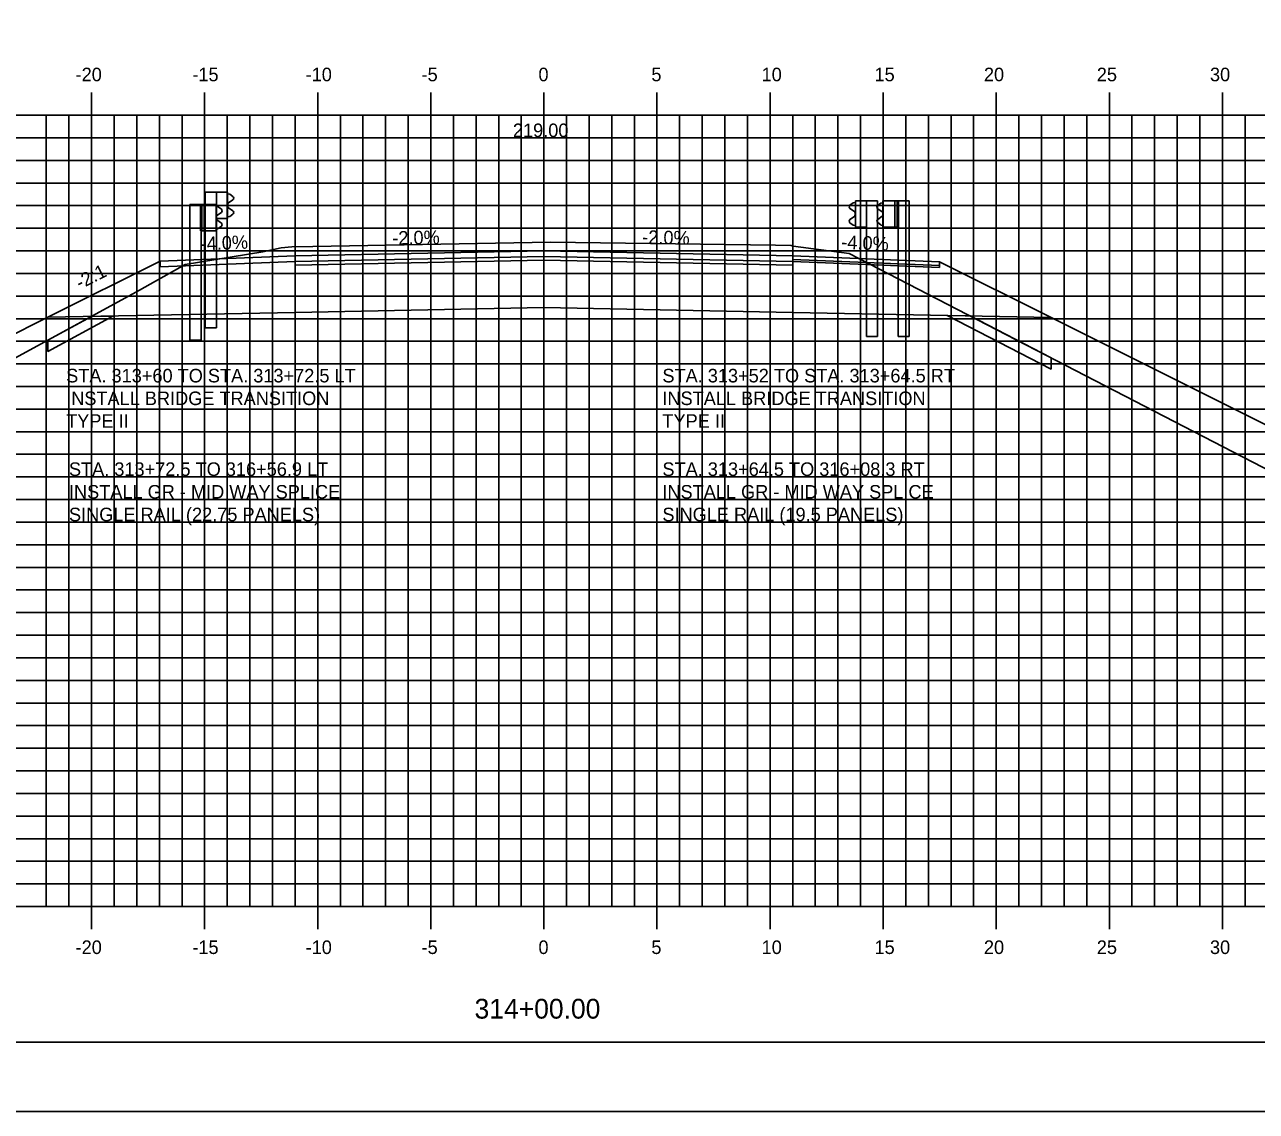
# Model space of a CAD drawing. Extents: x 1138320 to 1138490, y 608981 to 609091.
# Drawn here: x 1138379.7 to 1138434.2, y 608981.3 to 609029.3 of the extents above; entities that cross this region are included whole.
import ezdxf

# ---------------------------------------------------------------- set-up
doc = ezdxf.new("R2010")
doc.units = 0
for name, color, linetype in [('ANNOTATION', 7, 'Continuous'), ('BORDER', 7, 'Continuous'), ('D_Guardrail_Beam_Lt', 7, 'Continuous'), ('D_Guardrail_Beam_Rt', 7, 'Continuous'), ('D_Guardrail_ConcBarrier', 7, 'Continuous'), ('D_Roadway_Centerline', 7, 'Continuous'), ('D_Roadway_Centerline_Text', 7, 'Continuous'), ('D_Roadway_Edge_Shoulder', 7, 'Continuous'), ('D_Roadway_Edge_TW', 7, 'Continuous'), ('D_Roadway_Pavement', 7, 'Continuous'), ('D_Roadway_SlopeLines', 7, 'Continuous'), ('D_Roadway_SubGrade', 7, 'Continuous'), ('H_V ANNOTATION', 7, 'Continuous'), ('MAJOR', 7, 'Continuous'), ('MINOR', 7, 'Continuous'), ('PLOT BOUNDARY', 7, 'Continuous'), ('S_Guardrail_Beam', 7, 'Continuous'), ('S_Roadway_Centerline', 7, 'Continuous'), ('SHADING', 7, 'Continuous')]:
    doc.layers.add(name, color=color, linetype=linetype)

msp = doc.modelspace()

# ---------------------------------------------------------------- linework, layer by layer
msp.add_lwpolyline([(1138342.969, 608997.503), (1138378.753, 609015.395), (1138380.753, 609016.395), (1138385.713, 609018.875), (1138385.714, 609018.875), (1138391.679, 609019.113), (1138402.679, 609019.333), (1138413.679, 609019.113), (1138420.167, 609018.854), (1138425.105, 609016.385), (1138427.105, 609015.385), (1138461.719, 608998.078)])
at = {"layer": 'BORDER'}
msp.add_lwpolyline([(1138327.679, 608984.335), (1138487.679, 608984.335), (1138487.679, 609089.335), (1138327.679, 609089.335)], close=True, dxfattribs=at)
at = {"layer": 'D_Guardrail_Beam_Lt'}
for p, q in [((1138387.026, 609021.382), (1138387.026, 609015.382)), ((1138387.497, 609021.382), (1138387.026, 609021.382)), ((1138388.184, 609021.382), (1138387.497, 609021.382)), ((1138387.497, 609021.382), (1138387.497, 609020.216)), ((1138387.559, 609021.382), (1138387.559, 609020.216)), ((1138387.664, 609021.382), (1138387.664, 609020.216)), ((1138388.184, 609020.216), (1138388.184, 609021.382)), ((1138388.184, 609021.299), (1138388.259, 609021.285)), ((1138388.274, 609021.278), (1138388.418, 609021.178)), ((1138388.189, 609020.834), (1138388.189, 609020.764)), ((1138388.418, 609021.035), (1138388.223, 609020.899)), ((1138388.223, 609020.7), (1138388.418, 609020.563)), ((1138387.497, 609020.216), (1138388.184, 609020.216)), ((1138387.518, 609015.382), (1138387.518, 609020.216)), ((1138388.259, 609020.314), (1138388.184, 609020.299)), ((1138388.418, 609020.42), (1138388.274, 609020.32)), ((1138387.518, 609015.382), (1138387.026, 609015.382))]:
    msp.add_line(p, q, dxfattribs=at)
for centre, major_axis, start_param, end_param in [((1138388.251, 609021.244), (0.0417, 0), 0.959931, 1.376053), ((1138388.368, 609021.106), (0.0877, 0), 5.323254, 7.243116), ((1138388.268, 609020.834), (-0.0789, 0), 5.323254, 6.283185), ((1138388.268, 609020.764), (-0.0789, 0), 6.283185, 7.243116), ((1138388.251, 609020.354), (0.0417, 0), 4.907132, 5.323254), ((1138388.368, 609020.492), (0.0877, 0), 5.323254, 7.243116)]:
    msp.add_ellipse(centre, major_axis=major_axis, ratio=0.995501, start_param=start_param, end_param=end_param, dxfattribs=at)
at = {"layer": 'D_Guardrail_Beam_Rt'}
for p, q in [((1138417.58, 609021.44), (1138417.437, 609021.34)), ((1138417.437, 609021.197), (1138417.632, 609021.061)), ((1138417.67, 609021.462), (1138417.596, 609021.447)), ((1138417.632, 609020.862), (1138417.437, 609020.726)), ((1138417.666, 609020.997), (1138417.666, 609020.926)), ((1138417.437, 609020.583), (1138417.58, 609020.483)), ((1138417.596, 609020.476), (1138417.67, 609020.462))]:
    msp.add_line(p, q, dxfattribs=at)
for centre, major_axis, start_param, end_param in [((1138417.487, 609021.269), (-0.0877, 0), 5.323254, 7.243116), ((1138417.604, 609021.406), (-0.0417, 0), 4.907132, 5.323254), ((1138417.487, 609020.654), (-0.0877, 0), 5.323254, 7.243116), ((1138417.587, 609020.997), (0.0789, 0), 0, 0.959931), ((1138417.587, 609020.926), (0.0789, 0), 5.323254, 6.283185), ((1138417.604, 609020.517), (-0.0417, 0), 0.959931, 1.376053)]:
    msp.add_ellipse(centre, major_axis=major_axis, ratio=0.995501, start_param=start_param, end_param=end_param, dxfattribs=at)
at = {"layer": 'D_Guardrail_ConcBarrier'}
for p, q in [((1138417.67, 609021.545), (1138418.358, 609021.545)), ((1138417.67, 609020.378), (1138417.67, 609021.545)), ((1138418.191, 609021.545), (1138418.191, 609020.378)), ((1138418.295, 609021.545), (1138418.295, 609020.378)), ((1138418.358, 609021.545), (1138418.828, 609021.545)), ((1138418.358, 609021.545), (1138418.358, 609020.378)), ((1138418.828, 609021.545), (1138418.828, 609015.545)), ((1138418.358, 609020.378), (1138417.67, 609020.378)), ((1138418.337, 609015.545), (1138418.337, 609020.378)), ((1138418.337, 609015.545), (1138418.828, 609015.545))]:
    msp.add_line(p, q, dxfattribs=at)
at = {"layer": 'D_Roadway_Edge_Shoulder'}
for points in [[(1138391.679, 609019.113), (1138385.714, 609018.875), (1138385.714, 609018.625), (1138391.679, 609018.863)], [(1138413.679, 609019.113), (1138420.167, 609018.854), (1138420.167, 609018.687), (1138413.679, 609018.947)], [(1138413.679, 609019.113), (1138420.167, 609018.854), (1138420.167, 609018.604), (1138413.679, 609018.863)]]:
    msp.add_lwpolyline(points, close=True, dxfattribs=at)
at = {"layer": 'D_Roadway_Edge_TW'}
msp.add_lwpolyline([(1138391.679, 609018.863), (1138391.679, 609019.113), (1138402.679, 609019.333), (1138413.679, 609019.113), (1138413.679, 609018.863), (1138402.679, 609019.083)], close=True, dxfattribs=at)
at = {"layer": 'D_Roadway_Pavement'}
msp.add_lwpolyline([(1138391.679, 609018.697), (1138391.679, 609018.863), (1138402.679, 609019.083), (1138413.679, 609018.863), (1138413.679, 609018.697), (1138402.679, 609018.917)], close=True, dxfattribs=at)
at = {"layer": 'D_Roadway_SlopeLines'}
for points in [[(1138383.94, 609017.125), (1138383.94, 609017.125)], [(1138423.716, 609017.079), (1138461.719, 608998.078)], [(1138380.753, 609016.395), (1138378.753, 609015.395)], [(1138380.753, 609015.386), (1138380.753, 609014.886), (1138383.623, 609016.452)], [(1138425.105, 609014.602), (1138425.105, 609014.102), (1138420.512, 609016.477)], [(1138425.105, 609016.385), (1138427.105, 609015.385)], [(1138427.105, 609015.385), (1138461.719, 608998.078)]]:
    msp.add_lwpolyline(points, dxfattribs=at)
at = {"layer": 'D_Roadway_SubGrade'}
for points in [[(1138391.679, 609018.697), (1138391.679, 609018.863), (1138385.714, 609018.625), (1138385.714, 609018.875), (1138385.713, 609018.875), (1138380.753, 609016.395), (1138391.679, 609016.613)], [(1138391.679, 609016.613), (1138391.679, 609018.697), (1138402.679, 609018.917), (1138413.679, 609018.697), (1138413.679, 609016.613), (1138402.679, 609016.833)], [(1138413.679, 609018.697), (1138413.679, 609018.863), (1138420.167, 609018.604), (1138420.167, 609018.854), (1138420.167, 609018.854), (1138425.105, 609016.385), (1138413.679, 609016.613)]]:
    msp.add_lwpolyline(points, close=True, dxfattribs=at)
at = {"layer": 'MAJOR'}
for p, q in [((1138382.679, 609026.337), (1138382.679, 609025.335)), ((1138387.679, 609026.337), (1138387.679, 609025.335)), ((1138392.679, 609026.337), (1138392.679, 609025.335)), ((1138397.679, 609026.337), (1138397.679, 609025.335)), ((1138402.679, 609026.337), (1138402.679, 609025.335)), ((1138407.679, 609026.337), (1138407.679, 609025.335)), ((1138412.679, 609026.337), (1138412.679, 609025.335)), ((1138417.679, 609026.337), (1138417.679, 609025.335)), ((1138422.679, 609026.337), (1138422.679, 609025.335)), ((1138427.679, 609026.337), (1138427.679, 609025.335)), ((1138432.679, 609026.337), (1138432.679, 609025.335)), ((1138332.679, 609025.335), (1138472.679, 609025.335)), ((1138332.679, 609025.335), (1138472.679, 609025.335)), ((1138382.679, 608990.335), (1138382.679, 609025.335)), ((1138387.679, 608990.335), (1138387.679, 609025.335)), ((1138392.679, 608990.335), (1138392.679, 609025.335)), ((1138397.679, 608990.335), (1138397.679, 609025.335)), ((1138402.679, 608990.335), (1138402.679, 609025.335)), ((1138407.679, 608990.335), (1138407.679, 609025.335)), ((1138412.679, 608990.335), (1138412.679, 609025.335)), ((1138417.679, 608990.335), (1138417.679, 609025.335)), ((1138422.679, 608990.335), (1138422.679, 609025.335)), ((1138427.679, 608990.335), (1138427.679, 609025.335)), ((1138432.679, 608990.335), (1138432.679, 609025.335)), ((1138332.679, 609020.335), (1138472.679, 609020.335)), ((1138332.679, 609015.335), (1138472.679, 609015.335)), ((1138332.679, 609010.335), (1138472.679, 609010.335)), ((1138332.679, 609005.335), (1138472.679, 609005.335)), ((1138332.679, 609000.335), (1138472.679, 609000.335)), ((1138332.679, 608995.335), (1138472.679, 608995.335)), ((1138332.679, 608990.335), (1138472.679, 608990.335)), ((1138332.679, 608990.335), (1138472.679, 608990.335)), ((1138382.679, 608989.333), (1138382.679, 608990.335)), ((1138387.679, 608989.333), (1138387.679, 608990.335)), ((1138392.679, 608989.333), (1138392.679, 608990.335)), ((1138397.679, 608989.333), (1138397.679, 608990.335)), ((1138402.679, 608989.333), (1138402.679, 608990.335)), ((1138407.679, 608989.333), (1138407.679, 608990.335)), ((1138412.679, 608989.333), (1138412.679, 608990.335)), ((1138417.679, 608989.333), (1138417.679, 608990.335)), ((1138422.679, 608989.333), (1138422.679, 608990.335)), ((1138427.679, 608989.333), (1138427.679, 608990.335)), ((1138432.679, 608989.333), (1138432.679, 608990.335))]:
    msp.add_line(p, q, dxfattribs=at)
at = {"layer": 'MINOR'}
for p, q in [((1138380.679, 608990.335), (1138380.679, 609025.335)), ((1138381.679, 608990.335), (1138381.679, 609025.335)), ((1138383.679, 608990.335), (1138383.679, 609025.335)), ((1138384.679, 608990.335), (1138384.679, 609025.335)), ((1138385.679, 608990.335), (1138385.679, 609025.335)), ((1138386.679, 608990.335), (1138386.679, 609025.335)), ((1138388.679, 608990.335), (1138388.679, 609025.335)), ((1138389.679, 608990.335), (1138389.679, 609025.335)), ((1138390.679, 608990.335), (1138390.679, 609025.335)), ((1138391.679, 608990.335), (1138391.679, 609025.335)), ((1138393.679, 608990.335), (1138393.679, 609025.335)), ((1138394.679, 608990.335), (1138394.679, 609025.335)), ((1138395.679, 608990.335), (1138395.679, 609025.335)), ((1138396.679, 608990.335), (1138396.679, 609025.335)), ((1138398.679, 608990.335), (1138398.679, 609025.335)), ((1138399.679, 608990.335), (1138399.679, 609025.335)), ((1138400.679, 608990.335), (1138400.679, 609025.335)), ((1138401.679, 608990.335), (1138401.679, 609025.335)), ((1138403.679, 608990.335), (1138403.679, 609025.335)), ((1138404.679, 608990.335), (1138404.679, 609025.335)), ((1138405.679, 608990.335), (1138405.679, 609025.335)), ((1138406.679, 608990.335), (1138406.679, 609025.335)), ((1138408.679, 608990.335), (1138408.679, 609025.335)), ((1138409.679, 608990.335), (1138409.679, 609025.335)), ((1138410.679, 608990.335), (1138410.679, 609025.335)), ((1138411.679, 608990.335), (1138411.679, 609025.335)), ((1138413.679, 608990.335), (1138413.679, 609025.335)), ((1138414.679, 608990.335), (1138414.679, 609025.335)), ((1138415.679, 608990.335), (1138415.679, 609025.335)), ((1138416.679, 608990.335), (1138416.679, 609025.335)), ((1138418.679, 608990.335), (1138418.679, 609025.335)), ((1138419.679, 608990.335), (1138419.679, 609025.335)), ((1138420.679, 608990.335), (1138420.679, 609025.335)), ((1138421.679, 608990.335), (1138421.679, 609025.335)), ((1138423.679, 608990.335), (1138423.679, 609025.335)), ((1138424.679, 608990.335), (1138424.679, 609025.335)), ((1138425.679, 608990.335), (1138425.679, 609025.335)), ((1138426.679, 608990.335), (1138426.679, 609025.335)), ((1138428.679, 608990.335), (1138428.679, 609025.335)), ((1138429.679, 608990.335), (1138429.679, 609025.335)), ((1138430.679, 608990.335), (1138430.679, 609025.335)), ((1138431.679, 608990.335), (1138431.679, 609025.335)), ((1138433.679, 608990.335), (1138433.679, 609025.335)), ((1138332.679, 609024.335), (1138472.679, 609024.335)), ((1138332.679, 609023.335), (1138472.679, 609023.335)), ((1138332.679, 609022.335), (1138472.679, 609022.335)), ((1138332.679, 609021.335), (1138472.679, 609021.335)), ((1138332.679, 609019.335), (1138472.679, 609019.335)), ((1138332.679, 609018.335), (1138472.679, 609018.335)), ((1138332.679, 609017.335), (1138472.679, 609017.335)), ((1138332.679, 609016.335), (1138472.679, 609016.335)), ((1138332.679, 609014.335), (1138472.679, 609014.335)), ((1138332.679, 609013.335), (1138472.679, 609013.335)), ((1138332.679, 609012.335), (1138472.679, 609012.335)), ((1138332.679, 609011.335), (1138472.679, 609011.335)), ((1138332.679, 609009.335), (1138472.679, 609009.335)), ((1138332.679, 609008.335), (1138472.679, 609008.335)), ((1138332.679, 609007.335), (1138472.679, 609007.335)), ((1138332.679, 609006.335), (1138472.679, 609006.335)), ((1138332.679, 609004.335), (1138472.679, 609004.335)), ((1138332.679, 609003.335), (1138472.679, 609003.335)), ((1138332.679, 609002.335), (1138472.679, 609002.335)), ((1138332.679, 609001.335), (1138472.679, 609001.335)), ((1138332.679, 608999.335), (1138472.679, 608999.335)), ((1138332.679, 608998.335), (1138472.679, 608998.335)), ((1138332.679, 608997.335), (1138472.679, 608997.335)), ((1138332.679, 608996.335), (1138472.679, 608996.335)), ((1138332.679, 608994.335), (1138472.679, 608994.335)), ((1138332.679, 608993.335), (1138472.679, 608993.335)), ((1138332.679, 608992.335), (1138472.679, 608992.335)), ((1138332.679, 608991.335), (1138472.679, 608991.335))]:
    msp.add_line(p, q, dxfattribs=at)
at = {"layer": 'PLOT BOUNDARY'}
msp.add_lwpolyline([(1138319.586, 608981.276), (1138489.586, 608981.276), (1138489.586, 609091.276), (1138319.586, 609091.276)], close=True, dxfattribs=at)
at = {"layer": 'S_Guardrail_Beam'}
for p, q in [((1138387.707, 609021.932), (1138387.707, 609015.932)), ((1138388.199, 609021.932), (1138387.707, 609021.932)), ((1138388.689, 609021.932), (1138388.199, 609021.932)), ((1138388.199, 609021.932), (1138388.199, 609020.766)), ((1138388.689, 609020.766), (1138388.689, 609021.932)), ((1138388.689, 609021.859), (1138388.771, 609021.845)), ((1138388.787, 609021.838), (1138388.931, 609021.738)), ((1138388.702, 609021.394), (1138388.702, 609021.303)), ((1138388.931, 609021.595), (1138388.736, 609021.459)), ((1138388.736, 609021.239), (1138388.931, 609021.103)), ((1138416.354, 609021.455), (1138416.21, 609021.355)), ((1138416.21, 609021.212), (1138416.406, 609021.075)), ((1138416.453, 609021.476), (1138416.371, 609021.462)), ((1138416.453, 609021.549), (1138416.942, 609021.549)), ((1138416.453, 609020.382), (1138416.453, 609021.549)), ((1138416.942, 609021.549), (1138417.434, 609021.549)), ((1138416.942, 609021.549), (1138416.942, 609020.382)), ((1138417.434, 609021.549), (1138417.434, 609015.549)), ((1138388.199, 609015.932), (1138388.199, 609020.766)), ((1138388.199, 609020.766), (1138388.689, 609020.766)), ((1138388.771, 609020.853), (1138388.689, 609020.838)), ((1138388.931, 609020.96), (1138388.787, 609020.86)), ((1138416.406, 609020.856), (1138416.21, 609020.719)), ((1138416.439, 609021.011), (1138416.439, 609020.92)), ((1138416.21, 609020.576), (1138416.354, 609020.476)), ((1138416.371, 609020.47), (1138416.453, 609020.455)), ((1138416.942, 609020.382), (1138416.453, 609020.382)), ((1138416.942, 609015.549), (1138416.942, 609020.382)), ((1138388.199, 609015.932), (1138387.707, 609015.932)), ((1138416.942, 609015.549), (1138417.434, 609015.549))]:
    msp.add_line(p, q, dxfattribs=at)
for centre, major_axis, start_param, end_param in [((1138388.764, 609021.804), (0.0417, 0), 0.959931, 1.396263), ((1138388.881, 609021.667), (0.0877, 0), 5.323254, 7.243116), ((1138388.781, 609021.394), (-0.0789, 0), 5.323254, 6.283185), ((1138388.781, 609021.303), (-0.0789, 0), 6.283185, 7.243116), ((1138416.261, 609021.283), (-0.0877, 0), 5.323254, 7.243116), ((1138416.378, 609021.421), (-0.0417, 0), 4.886922, 5.323254), ((1138388.764, 609020.894), (0.0417, 0), 4.886922, 5.323254), ((1138388.881, 609021.031), (0.0877, 0), 5.323254, 7.243116), ((1138416.261, 609020.648), (-0.0877, 0), 5.323254, 7.243116), ((1138416.361, 609021.011), (0.0789, 0), 0, 0.959931), ((1138416.361, 609020.92), (0.0789, 0), 5.323254, 6.283185), ((1138416.378, 609020.51), (-0.0417, 0), 0.959931, 1.396263)]:
    msp.add_ellipse(centre, major_axis=major_axis, ratio=0.995501, start_param=start_param, end_param=end_param, dxfattribs=at)
at = {"layer": 'S_Roadway_Centerline'}
msp.add_lwpolyline([(1138366.825, 609007.787), (1138384.799, 609017.593), (1138386.824, 609018.729), (1138390.25, 609019.291), (1138391.066, 609019.463), (1138391.53, 609019.519), (1138392.468, 609019.533), (1138402.971, 609019.723), (1138412.915, 609019.586), (1138413.616, 609019.576), (1138413.704, 609019.537), (1138416.182, 609019.216), (1138447.504, 609003.02), (1138456.197, 608998.757), (1138456.912, 608998.64), (1138457.654, 608998.458), (1138458.603, 608998.167), (1138458.832, 608998.129), (1138459.426, 608998.129), (1138472.679, 608997.833)], dxfattribs=at)
at = {"layer": 'SHADING'}
for p, q in [((1138382.672, 609016.433), (1138380.753, 609015.386)), ((1138383.623, 609016.452), (1138382.672, 609016.433)), ((1138421.518, 609016.457), (1138420.512, 609016.477)), ((1138425.105, 609014.602), (1138421.518, 609016.457))]:
    msp.add_line(p, q, dxfattribs=at)
for points in [[(1138380.753, 609015.386), (1138380.753, 609014.886), (1138383.623, 609016.452)], [(1138420.512, 609016.477), (1138425.105, 609014.102), (1138425.105, 609014.602)]]:
    msp.add_lwpolyline(points, dxfattribs=at)

# ---------------------------------------------------------------- texts
at = {"layer": 'ANNOTATION'}
for s, rotation, p in [('-2.0%', 1.1458, (1138395.982, 609019.6)), ('-2.0%', 358.8542, (1138407.022, 609019.647)), ('-4.0%', 2.2906, (1138387.512, 609019.347)), ('-4.0%', 357.7094, (1138415.819, 609019.429)), ('-2:1', 26.5651, (1138382.162, 609017.617))]:
    msp.add_text(s, height=0.6, rotation=rotation, dxfattribs=at).set_placement(p)
for s, p in [('STA. 313+60 TO STA. 313+72.5 LT', (1138381.557, 609013.515)), ('STA. 313+52 TO STA. 313+64.5 RT', (1138407.918, 609013.515)), ('INSTALL BRIDGE TRANSITION', (1138381.557, 609012.513)), ('INSTALL BRIDGE TRANSITION', (1138407.918, 609012.513)), ('TYPE II', (1138381.557, 609011.511)), ('TYPE II', (1138407.918, 609011.511)), ('STA. 313+72.5 TO 316+56.9 LT', (1138381.68, 609009.379)), ('STA. 313+64.5 TO 316+08.3 RT', (1138407.918, 609009.379)), ('INSTALL GR - MID WAY SPLICE', (1138381.68, 609008.377)), ('INSTALL GR - MID WAY SPLICE', (1138407.918, 609008.377)), ('SINGLE RAIL (22.75 PANELS)', (1138381.68, 609007.375)), ('SINGLE RAIL (19.5 PANELS)', (1138407.918, 609007.375))]:
    msp.add_text(s, height=0.6, dxfattribs=at).set_placement(p)
at = {"layer": 'D_Roadway_Centerline'}
for s, p in [('C', (1138402.674, 609019.333)), ('L', (1138402.679, 609019.326))]:
    msp.add_text(s, height=0.0146, dxfattribs=at).set_placement(p)
at = {"layer": 'D_Roadway_Centerline_Text'}
msp.add_text('219.00', height=0.6, dxfattribs=at).set_placement((1138401.309, 609024.365))
at = {"layer": 'H_V ANNOTATION'}
for s, height, p in [('-20', 0.6, (1138381.973, 609026.835)), ('-15', 0.6, (1138387.136, 609026.835)), ('-10', 0.6, (1138392.144, 609026.835)), ('-5', 0.6, (1138397.27, 609026.835)), ('0', 0.6, (1138402.438, 609026.835)), ('5', 0.6, (1138407.43, 609026.835)), ('10', 0.6, (1138412.304, 609026.835)), ('15', 0.6, (1138417.296, 609026.835)), ('20', 0.6, (1138422.133, 609026.835)), ('25', 0.6, (1138427.125, 609026.835)), ('30', 0.6, (1138432.128, 609026.835)), ('-20', 0.6, (1138381.973, 608988.235)), ('-15', 0.6, (1138387.136, 608988.235)), ('-10', 0.6, (1138392.144, 608988.235)), ('-5', 0.6, (1138397.27, 608988.235)), ('0', 0.6, (1138402.438, 608988.235)), ('5', 0.6, (1138407.43, 608988.235)), ('10', 0.6, (1138412.304, 608988.235)), ('15', 0.6, (1138417.296, 608988.235)), ('20', 0.6, (1138422.133, 608988.235)), ('25', 0.6, (1138427.125, 608988.235)), ('30', 0.6, (1138432.128, 608988.235)), ('314+00.00', 0.875, (1138399.613, 608985.378))]:
    msp.add_text(s, height=height, dxfattribs=at).set_placement(p)
at = {"layer": 'S_Roadway_Centerline'}
for s, p in [('C', (1138402.966, 609019.723)), ('L', (1138402.971, 609019.716))]:
    msp.add_text(s, height=0.0146, dxfattribs=at).set_placement(p)

doc.saveas('drawing.dxf')
